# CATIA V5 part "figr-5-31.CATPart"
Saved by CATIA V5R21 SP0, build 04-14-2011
Part number: Part1
Bounding box of the stored display mesh (mm): x -32.491 to 32.491, y -32.393 to 32.5, z 0 to 91.19
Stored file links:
  D:\CATIA V5R21 E-RESOURCES\CATIA-V5R21\catia-v5r21-prt\c05-catia-v5r20-prt\catia-v5r21-figr-5-31.CATPart
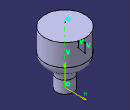
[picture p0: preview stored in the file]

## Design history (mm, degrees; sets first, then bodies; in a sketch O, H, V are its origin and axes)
Body1 (main body)
  Sketch1 on yz-plane, origin (0, 0, 0), H (0, 1, 0), V (0, 0, 1)
    axis line L1 (0, 0) -> (0, 100.0993)
    line L2 (0, 0) -> (13.3295, 0)
    line L3 (13.3295, 0) -> (13.3295, 19.6564)
    arc A1 centre (31.7623, 19.6564) radius 18.4328 from (13.3295, 19.6564) to (23.518, 36.1427) cw
    arc A2 centre (16.25, 50.6768) radius 16.25 from (23.518, 36.1427) to (32.5, 50.6768) ccw
    line L4 (32.5, 50.6768) -> (32.5, 85.6563)
    line L5 (32.5, 85.6563) -> (0, 85.6563)
    point P9 (0, 85.6563)
    line L6 (0, 85.6563) -> (0, 0)
    "Radius" L4 L1 = 32.5
    vertical: L1 V, L3 V, L4 V
    horizontal: L2 H, L5 H
    tangency: A1 L3, A2 L1, A2 A1, L4 A2, L6 A2
    coincidence: P9 L1
  Shaft1: profile Sketch1, axis Sketch1.L1, angle 360
  Sketch2 on yz-plane, origin (0, 0, 0), H (0, 1, 0), V (0, 0, 1)
    axis line L1 (0, 0) -> (0, 91.1904)
    point P1 (0, 0)
    point P2 (0, 91.1904)
    line L2 (32.5, 78.7512) -> (21.4593, 75.7196)
    line L3 (21.4593, 75.7196) -> (21.4593, 66.4534)
    line L4 (21.4593, 66.4534) -> (32.5, 63.9927)
    line L5 (32.5, 63.9927) -> (32.5, 78.7512)
    coincidence: P1 H, P2 V
    vertical: L1 V, L3 V, L5 V
  Groove1: profile Sketch2, axis Sketch2.L1, angle 360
